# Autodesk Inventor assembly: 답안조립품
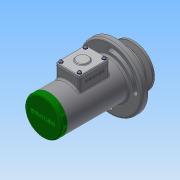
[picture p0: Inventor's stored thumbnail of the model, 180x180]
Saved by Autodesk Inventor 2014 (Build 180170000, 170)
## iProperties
Created: 2017-05
Part Number: 답안조립품
Document SubType Name: Assembly
Designer: SCD-A14
Author: SCD-A14
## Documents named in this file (20)
- C:\Users\SCD-A14\Desktop\470508V1008\답안조립품.iam
- C:\Users\SCD-A14\Desktop\470508V1008\본체.ipt
- C:\Users\SCD-A14\Desktop\470508V1008\사이드 커버.ipt
- 사이드 커버.ipt
- C:\Users\SCD-A14\Desktop\470508V1008\축.ipt
- C:\Users\SCD-A14\Desktop\470508V1008\부시1.ipt
- C:\Users\SCD-A14\Desktop\470508V1008\베어링 15 x 35 x 11.ipt
- C:\Users\SCD-A14\Desktop\470508V1008\멈춤링 35x1.6.ipt
- C:\Users\SCD-A14\Desktop\470508V1008\부시2.ipt
- C:\Users\SCD-A14\Desktop\470508V1008\와셔 10x21.ipt
- C:\Users\SCD-A14\Desktop\470508V1008\너트 M10.ipt
- C:\Users\SCD-A14\Desktop\470508V1008\멈춤링 15 x 1.ipt
- C:\Users\SCD-A14\Desktop\470508V1008\오일 실 15 25 7.ipt
- C:\Users\SCD-A14\Desktop\470508V1008\V-벨트풀리.ipt
- C:\Users\SCD-A14\Desktop\470508V1008\키 4 x 4 x 18.ipt
- C:\Users\SCD-A14\Desktop\470508V1008\와셔 4x16.ipt
- C:\Users\SCD-A14\Desktop\470508V1008\볼트 M4 x 10.ipt
- C:\Users\SCD-A14\Desktop\470508V1008\탑 커버.ipt
- C:\Users\SCD-A14\Desktop\470508V1008\와셔 3x6.ipt
- C:\Users\SCD-A14\Desktop\470508V1008\십자볼트 M3 x 10.ipt
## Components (2 placed, 2 different names)
1. V-벨트풀리:1 — 각도:2
2. ISO 4017 M4 x 10:1
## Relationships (1: Angle 1)
- 각도:2 [Angle]: V-벨트풀리:1
